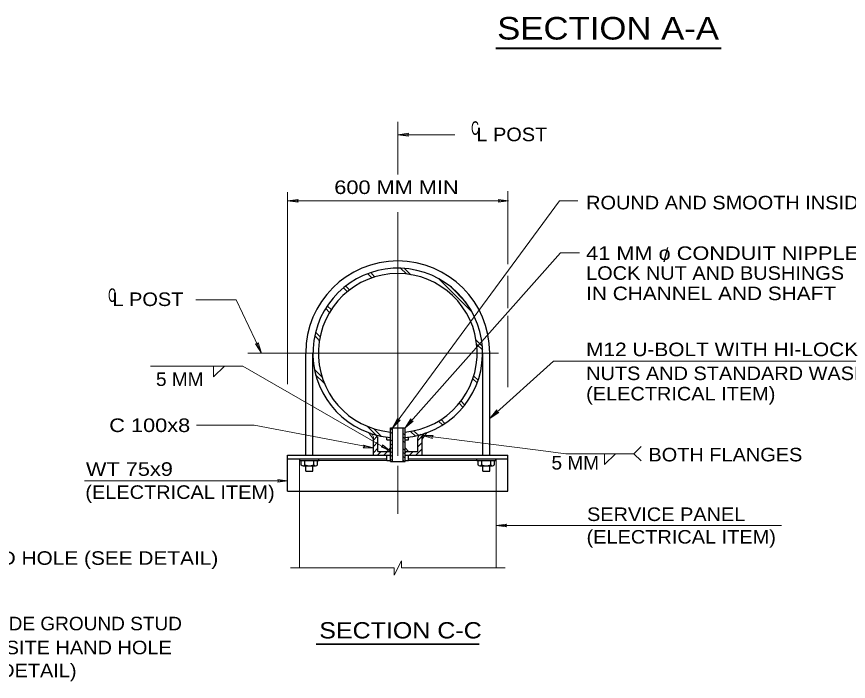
# Model space of a CAD drawing. Extents: x 312601.858 to 312602.699, y 144420.109 to 144420.704.
# Drawn here: x 312602.1557 to 312602.3399, y 144420.3327 to 144420.4799 of the extents above; entities that cross this region are included whole.
import ezdxf
from ezdxf.enums import TextEntityAlignment as Align

# ---------------------------------------------------------------- set-up
doc = ezdxf.new("R2010")
doc.units = 0
doc.header["$LTSCALE"] = 0.0012
doc.linetypes.add('LONG_DASH_SHORT_DASH', pattern=[9.9, 6, -1.2, 1.5, -1.2])
doc.linetypes.add('LONG_DASHED', pattern=[7.5, 6, -1.5])
for name, color, linetype, lineweight in [('1', 7, 'Continuous', 25), ('2', 7, 'Continuous', 25), ('39', 7, 'Continuous', 13)]:
    doc.layers.add(name, color=color, linetype=linetype, lineweight=lineweight)

msp = doc.modelspace()

# ---------------------------------------------------------------- hatches: boundary and pattern name
at = {"layer": '39'}
for points in [[(312602.2423, 144420.4537), (312602.2425, 144420.4534), (312602.2401, 144420.4537), (312602.2425, 144420.4541)], [(312602.209, 144420.4074), (312602.2092, 144420.4077), (312602.2099, 144420.4054), (312602.2086, 144420.4074)], [(312602.2621, 144420.3924), (312602.2625, 144420.3922), (312602.2605, 144420.3909), (312602.262, 144420.3928)], [(312602.2402, 144420.3905), (312602.2406, 144420.3905), (312602.2389, 144420.3888), (312602.24, 144420.3909)], [(312602.2431, 144420.3904), (312602.2435, 144420.3903), (312602.2417, 144420.3888), (312602.243, 144420.3908)]]:
    msp.add_hatch(color=256, dxfattribs=at).paths.add_polyline_path(points)

# ---------------------------------------------------------------- linework, layer by layer
at = {"layer": '1', "lineweight": 40}
msp.add_line((312602.2618, 144420.4729), (312602.3117, 144420.4729), dxfattribs=at)
at = {"layer": '1', "lineweight": 13}
for p, q in [((312602.2401, 144420.4449), (312602.2401, 144420.4566)), ((312602.2401, 144420.4537), (312602.2527, 144420.4537)), ((312602.2157, 144420.3985), (312602.2157, 144420.441)), ((312602.2645, 144420.4412), (312602.2645, 144420.4251)), ((312602.2157, 144420.4391), (312602.2645, 144420.4391)), ((312602.2389, 144420.3888), (312602.2759, 144420.4391)), ((312602.2759, 144420.4391), (312602.28, 144420.4391)), ((312602.2417, 144420.3888), (312602.2761, 144420.4276)), ((312602.2344, 144420.422), (312602.2334, 144420.423)), ((312602.235, 144420.4222), (312602.2341, 144420.4232)), ((312602.242, 144420.4229), (312602.2407, 144420.4242)), ((312602.243, 144420.4227), (312602.2416, 144420.4241)), ((312602.2565, 144420.4145), (312602.2491, 144420.4219)), ((312602.2645, 144420.4225), (312602.2645, 144420.4153)), ((312602.2289, 144420.419), (312602.2281, 144420.4198)), ((312602.2294, 144420.4194), (312602.2286, 144420.4202)), ((312602.2552, 144420.4166), (312602.2517, 144420.4202)), ((312602.1954, 144420.4172), (312602.2043, 144420.4172)), ((312602.2253, 144420.415), (312602.2245, 144420.4158)), ((312602.225, 144420.4144), (312602.2241, 144420.4153)), ((312602.2645, 144420.4136), (312602.2645, 144420.3978)), ((312602.2227, 144420.4082), (312602.2217, 144420.4093)), ((312602.2229, 144420.409), (312602.2219, 144420.41)), ((312602.2588, 144420.4069), (312602.2574, 144420.4083)), ((312602.2589, 144420.406), (312602.2576, 144420.4073)), ((312602.2605, 144420.3909), (312602.2746, 144420.4036)), ((312602.2746, 144420.4036), (312602.3524, 144420.4036)), ((312602.1853, 144420.4025), (312602.2058, 144420.4025)), ((312602.2385, 144420.3837), (312602.2058, 144420.4025)), ((312602.2234, 144420.4), (312602.2217, 144420.4017)), ((312602.2238, 144420.3987), (312602.2219, 144420.4006)), ((312602.2577, 144420.3988), (312602.2567, 144420.3997)), ((312602.2579, 144420.3994), (312602.2569, 144420.4003)), ((312602.2545, 144420.3934), (312602.2537, 144420.3943)), ((312602.2549, 144420.3939), (312602.2541, 144420.3947)), ((312602.25, 144420.3895), (312602.2491, 144420.3903)), ((312602.2505, 144420.3898), (312602.2497, 144420.3907)), ((312602.1955, 144420.3894), (312602.2083, 144420.3894)), ((312602.2347, 144420.3844), (312602.2083, 144420.3894)), ((312602.2353, 144420.3872), (312602.2333, 144420.3892)), ((312602.2364, 144420.387), (312602.2347, 144420.3887)), ((312602.2389, 144420.3883), (312602.2385, 144420.3887)), ((312602.244, 144420.387), (312602.2429, 144420.388)), ((312602.2447, 144420.3872), (312602.2436, 144420.3882)), ((312602.2347, 144420.3863), (312602.2336, 144420.3878)), ((312602.2347, 144420.3861), (312602.2355, 144420.387)), ((312602.2389, 144420.3875), (312602.2385, 144420.3879)), ((312602.2389, 144420.3858), (312602.2385, 144420.3862)), ((312602.2417, 144420.3872), (312602.2413, 144420.3876)), ((312602.2417, 144420.3864), (312602.2413, 144420.3868)), ((312602.2445, 144420.386), (312602.246, 144420.3876)), ((312602.2466, 144420.3878), (312602.2455, 144420.3863)), ((312602.2455, 144420.3863), (312602.2466, 144420.3878)), ((312602.2456, 144420.3871), (312602.2712, 144420.3839)), ((312602.2347, 144420.3847), (312602.2357, 144420.3857)), ((312602.2347, 144420.3833), (312602.2357, 144420.3843)), ((312602.2389, 144420.3849), (312602.2385, 144420.3853)), ((312602.2389, 144420.3841), (312602.2385, 144420.3845)), ((312602.2417, 144420.3855), (312602.2413, 144420.3859)), ((312602.2445, 144420.3846), (312602.2455, 144420.3856)), ((312602.2924, 144420.3831), (312602.294, 144420.3847)), ((312602.2356, 144420.3828), (312602.2364, 144420.3836)), ((312602.237, 144420.3828), (312602.2378, 144420.3836)), ((312602.2389, 144420.3832), (312602.2385, 144420.3836)), ((312602.2389, 144420.3824), (312602.2385, 144420.3828)), ((312602.2417, 144420.3838), (312602.2413, 144420.3842)), ((312602.2417, 144420.383), (312602.2413, 144420.3834)), ((312602.2417, 144420.3821), (312602.2413, 144420.3825)), ((312602.2417, 144420.3833), (312602.2421, 144420.3836)), ((312602.2427, 144420.3828), (312602.2435, 144420.3836)), ((312602.2441, 144420.3828), (312602.2455, 144420.3842)), ((312602.2712, 144420.3839), (312602.2773, 144420.3831)), ((312602.2773, 144420.3831), (312602.2924, 144420.3831)), ((312602.2924, 144420.3831), (312602.294, 144420.3815)), ((312602.2389, 144420.3815), (312602.2385, 144420.3819)), ((312602.2415, 144420.3814), (312602.2413, 144420.3817)), ((312602.2401, 144420.3698), (312602.2401, 144420.3804)), ((312602.1707, 144420.3771), (312602.2157, 144420.3771)), ((312602.2619, 144420.3672), (312602.3251, 144420.3672)), ((312602.2393, 144420.3562), (312602.2409, 144420.3594)), ((312602.2409, 144420.3578), (312602.2409, 144420.3594)), ((312602.2163, 144420.3578), (312602.2393, 144420.3578)), ((312602.2393, 144420.3562), (312602.2393, 144420.3578)), ((312602.2409, 144420.3578), (312602.2639, 144420.3578))]:
    msp.add_line(p, q, dxfattribs=at)
at = {"layer": '1', "linetype": 'LONG_DASH_SHORT_DASH', "lineweight": 13}
for p, q in [((312602.2401, 144420.3826), (312602.2401, 144420.4366)), ((312602.2069, 144420.4054), (312602.2624, 144420.4054))]:
    msp.add_line(p, q, dxfattribs=at)
at = {"layer": '1'}
for p, q in [((312602.2197, 144420.3828), (312602.2197, 144420.4054)), ((312602.2213, 144420.3828), (312602.2213, 144420.4054)), ((312602.2589, 144420.3828), (312602.2589, 144420.4054)), ((312602.2605, 144420.3828), (312602.2605, 144420.4054)), ((312602.2385, 144420.3814), (312602.2385, 144420.3888)), ((312602.2385, 144420.3888), (312602.2417, 144420.3888)), ((312602.2389, 144420.3814), (312602.2389, 144420.3888)), ((312602.2413, 144420.3814), (312602.2413, 144420.3888)), ((312602.2417, 144420.3814), (312602.2417, 144420.3888)), ((312602.2357, 144420.3836), (312602.2357, 144420.3864)), ((312602.2377, 144420.3862), (312602.2377, 144420.3868)), ((312602.2377, 144420.3862), (312602.2385, 144420.3862)), ((312602.2417, 144420.3862), (312602.2425, 144420.3862)), ((312602.2425, 144420.3862), (312602.2425, 144420.3868)), ((312602.2445, 144420.3836), (312602.2445, 144420.3864)), ((312602.2455, 144420.3828), (312602.2455, 144420.3867)), ((312602.2157, 144420.3748), (312602.2157, 144420.3828)), ((312602.2157, 144420.3828), (312602.2385, 144420.3828)), ((312602.2357, 144420.3836), (312602.2385, 144420.3836)), ((312602.2377, 144420.3816), (312602.2377, 144420.3828)), ((312602.2417, 144420.3836), (312602.2445, 144420.3836)), ((312602.2417, 144420.3828), (312602.2645, 144420.3828)), ((312602.2425, 144420.3816), (312602.2425, 144420.3828)), ((312602.2157, 144420.382), (312602.2377, 144420.382)), ((312602.2184, 144420.3816), (312602.2184, 144420.382)), ((312602.2184, 144420.3816), (312602.2227, 144420.3816)), ((312602.2187, 144420.3806), (312602.2187, 144420.3816)), ((312602.2195, 144420.3806), (312602.2195, 144420.3816)), ((312602.2215, 144420.3806), (312602.2215, 144420.3816)), ((312602.2223, 144420.3806), (312602.2223, 144420.3816)), ((312602.2226, 144420.3816), (312602.2226, 144420.382)), ((312602.2377, 144420.3816), (312602.2385, 144420.3816)), ((312602.2385, 144420.3814), (312602.2417, 144420.3814)), ((312602.2417, 144420.3816), (312602.2425, 144420.3816)), ((312602.2425, 144420.382), (312602.2645, 144420.382)), ((312602.2576, 144420.3816), (312602.2576, 144420.382)), ((312602.2576, 144420.3816), (312602.2618, 144420.3816)), ((312602.2579, 144420.3806), (312602.2579, 144420.3816)), ((312602.2587, 144420.3806), (312602.2587, 144420.3816)), ((312602.2607, 144420.3806), (312602.2607, 144420.3816)), ((312602.2615, 144420.3806), (312602.2615, 144420.3816)), ((312602.2618, 144420.3816), (312602.2618, 144420.382)), ((312602.2191, 144420.3804), (312602.2219, 144420.3804)), ((312602.2197, 144420.3792), (312602.2197, 144420.3804)), ((312602.2197, 144420.3792), (312602.2213, 144420.3792)), ((312602.2213, 144420.3792), (312602.2213, 144420.3804)), ((312602.2583, 144420.3804), (312602.2611, 144420.3804)), ((312602.2589, 144420.3792), (312602.2589, 144420.3804)), ((312602.2589, 144420.3792), (312602.2605, 144420.3792)), ((312602.2605, 144420.3792), (312602.2605, 144420.3804))]:
    msp.add_line(p, q, dxfattribs=at)
at = {"layer": '1', "linetype": 'LONG_DASHED', "lineweight": 13}
for p, q in [((312602.2183, 144420.3578), (312602.2183, 144420.382)), ((312602.2223, 144420.3816), (312602.2377, 144420.3816)), ((312602.2425, 144420.3816), (312602.2578, 144420.3816)), ((312602.2619, 144420.3578), (312602.2619, 144420.382))]:
    msp.add_line(p, q, dxfattribs=at)
at = {"layer": '1', "lineweight": 35}
msp.add_line((312602.222, 144420.3409), (312602.2581, 144420.3409), dxfattribs=at)
at = {"layer": '1', "lineweight": 13}
for points in [[(312602.218, 144420.4388), (312602.2157, 144420.4391), (312602.218, 144420.4394), (312602.2177, 144420.4391)], [(312602.2624, 144420.4394), (312602.2646, 144420.4391), (312602.2624, 144420.4388), (312602.2626, 144420.4391)], [(312602.2478, 144420.3865), (312602.2456, 144420.3871), (312602.2479, 144420.3871), (312602.2476, 144420.3868)], [(312602.2325, 144420.385), (312602.2347, 144420.3844), (312602.2324, 144420.3844), (312602.2327, 144420.3847)], [(312602.2367, 144420.3851), (312602.2385, 144420.3837), (312602.2364, 144420.3846), (312602.2367, 144420.3847)], [(312602.2377, 144420.3836), (312602.2385, 144420.3844), (312602.2385, 144420.3836)], [(312602.2417, 144420.3844), (312602.2425, 144420.3836), (312602.2417, 144420.3836)], [(312602.2135, 144420.3774), (312602.2157, 144420.3771), (312602.2135, 144420.3768), (312602.2137, 144420.3771)], [(312602.2642, 144420.3669), (312602.2619, 144420.3672), (312602.2642, 144420.3675), (312602.2639, 144420.3672)]]:
    msp.add_lwpolyline(points, close=True, dxfattribs=at)
for points in [[(312602.1993, 144420.4025), (312602.1993, 144420.4001), (312602.2017, 144420.4025)], [(312602.2859, 144420.3831), (312602.2859, 144420.3807), (312602.2883, 144420.3831)]]:
    msp.add_lwpolyline(points, dxfattribs=at)
at = {"layer": '1'}
for points in [[(312602.2347, 144420.3828), (312602.2347, 144420.3864), (312602.2347, 144420.3867)], [(312602.2157, 144420.3748), (312602.2645, 144420.3748), (312602.2645, 144420.3828)]]:
    msp.add_lwpolyline(points, dxfattribs=at)
for centre, radius, start, end in [((312602.240085, 144420.4054), 0.020381, 0, 180), ((312602.240085, 144420.4054), 0.018783, 274.88214, 249.8914), ((312602.240085, 144420.4054), 0.017584, 275.21591, 264.78409), ((312602.240085, 144420.4054), 0.018783, 251.41898, 265.11786), ((312602.23469, 144420.386368), 0.000999, 0, 74.17338), ((312602.24548, 144420.386368), 0.000999, 105.82662, 180), ((312602.246479, 144420.38668), 0.000999, 108.85851, 180), ((312602.219104, 144420.380923), 0.0005, 216.8699, 323.1301), ((312602.220503, 144420.383021), 0.002598, 247.38014, 292.61987), ((312602.221902, 144420.380923), 0.0005, 216.8699, 323.1301), ((312602.258268, 144420.380923), 0.0005, 216.8699, 323.1301), ((312602.259667, 144420.383021), 0.002598, 247.38014, 292.61987), ((312602.261065, 144420.380923), 0.0005, 216.8699, 323.1301)]:
    msp.add_arc(centre, radius, start, end, dxfattribs=at)
at = {"layer": '1', "lineweight": 13}
for centre, radius, start, end in [((312602.240085, 144420.4054), 0.018783, 249.98785, 251.14149), ((312602.233691, 144420.38668), 0.000999, 0, 71.14635), ((312602.246509, 144420.38668), 0.000999, 108.85365, 180), ((312602.240115, 144420.4054), 0.018783, 288.85851, 290.01215)]:
    msp.add_arc(centre, radius, start, end, dxfattribs=at)
at = {"layer": '2', "lineweight": 13}
for p, q in [((312602.2803, 144420.4276), (312602.2761, 144420.4276)), ((312602.2043, 144420.4172), (312602.2099, 144420.4054))]:
    msp.add_line(p, q, dxfattribs=at)
at = {"layer": '39'}
for points in [[(312602.2423, 144420.4537), (312602.2425, 144420.4534), (312602.2401, 144420.4537), (312602.2425, 144420.4541)], [(312602.209, 144420.4074), (312602.2092, 144420.4077), (312602.2099, 144420.4054), (312602.2086, 144420.4074)], [(312602.2621, 144420.3924), (312602.2625, 144420.3922), (312602.2605, 144420.3909), (312602.262, 144420.3928)], [(312602.2402, 144420.3905), (312602.2406, 144420.3905), (312602.2389, 144420.3888), (312602.24, 144420.3909)], [(312602.2431, 144420.3904), (312602.2435, 144420.3903), (312602.2417, 144420.3888), (312602.243, 144420.3908)]]:
    msp.add_lwpolyline(points, close=True, dxfattribs=at)

# ---------------------------------------------------------------- texts
at = {"layer": '1'}
for s, height, width, p in [('ROUND AND SMOOTH INSIDE EDGE', 0.003, 1.1, (312602.2818, 144420.4372)), ('41 MM o CONDUIT NIPPLE, 125 MM LONG', 0.003, 1.2, (312602.2818, 144420.426)), ('LOCK NUT AND BUSHINGS', 0.003, 1.1, (312602.2818, 144420.4216)), ('IN CHANNEL AND SHAFT', 0.003, 1.15, (312602.2818, 144420.4171)), ('M12 U-BOLT WITH HI-LOCK', 0.003, 1.15, (312602.2818, 144420.4047)), ('NUTS AND STANDARD WASHERS', 0.003, 1.1, (312602.2818, 144420.3994)), ('(ELECTRICAL ITEM)', 0.003, 1.1, (312602.2818, 144420.3949)), ('BOTH FLANGES', 0.003, 1.1, (312602.2956, 144420.3814)), ('(ELECTRICAL ITEM)', 0.003, 1.1, (312602.1709, 144420.3731)), ('SERVICE PANEL', 0.003, 1.1, (312602.282, 144420.3682)), ('(ELECTRICAL ITEM)', 0.003, 1.1, (312602.2819, 144420.3632)), ('SECTION C-C', 0.0036, 1.15, (312602.2227, 144420.3422))]:
    msp.add_text(s, height=height, dxfattribs=dict(at, width=width)).set_placement(p)
at = {"layer": '2'}
for s, height, width, p in [('SECTION A-A', 0.005, 1.15, (312602.2621, 144420.4748)), ('HAND HOLE (SEE DETAIL)', 0.003, 1.15, (312602.1424, 144420.3585)), ('PROVIDE GROUND STUD', 0.003, 1.05, (312602.1408, 144420.344)), ('OPPOSITE HAND HOLE', 0.003, 1.1, (312602.1405, 144420.3387)), ('(SEE DETAIL)', 0.003, 1.1, (312602.1405, 144420.3336))]:
    msp.add_text(s, height=height, dxfattribs=dict(at, width=width)).set_placement(p)
for s, width, p in [('C', 0.6, (312602.2572, 144420.4537)), ('L POST', 1.1, (312602.26535, 144420.4523)), ('600 MM MIN', 1.2, (312602.2398, 144420.4406)), ('C', 0.6, (312602.1768, 144420.4167)), ('L POST', 1.1, (312602.18475, 144420.4158)), ('5 MM', 1.05, (312602.1918, 144420.3981)), ('C 100x8', 1.2, (312602.18515, 144420.3879)), ('5 MM', 1.05, (312602.2794, 144420.3796)), ('WT 75x9', 1.2, (312602.18065, 144420.3782))]:
    msp.add_text(s, height=0.003, dxfattribs=dict(at, width=width)).set_placement(p, align=Align.CENTER)
msp.add_text('/', height=0.003, dxfattribs=at).set_placement((312602.29945, 144420.4256), align=Align.CENTER)

doc.saveas('drawing.dxf')
